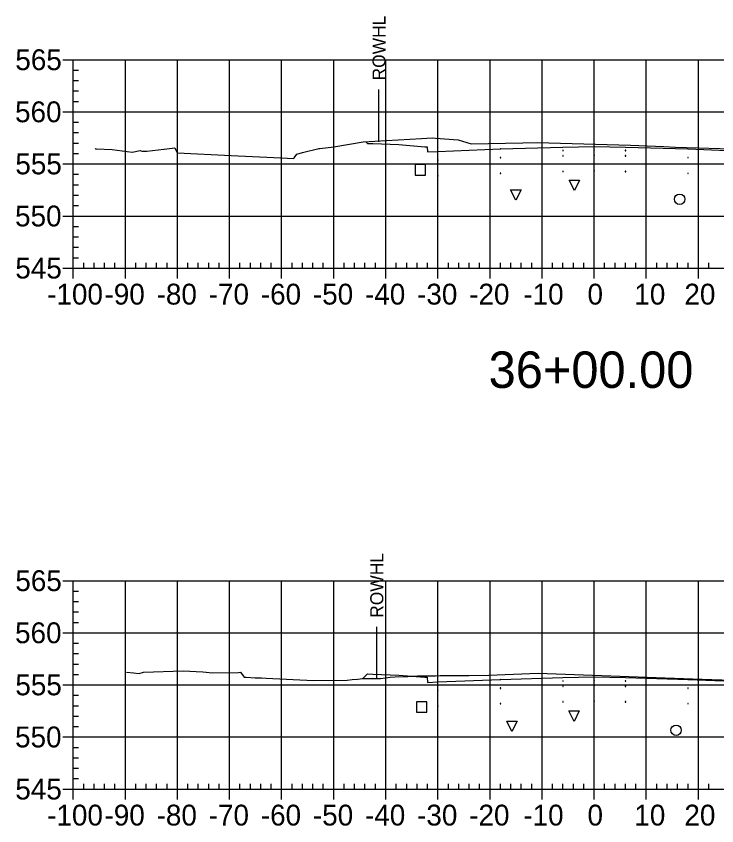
# Model space of a CAD drawing. Extents: x 708103 to 717568, y 374476 to 378707.
# Drawn here: x 710866 to 711000.5, y 377687.6 to 377843 of the extents above; entities that cross this region are included whole.
import ezdxf

# ---------------------------------------------------------------- set-up
doc = ezdxf.new("R2010")
doc.units = 0
for name, color, linetype in [('1', 7, 'Continuous'), ('10', 7, 'Continuous'), ('13', 7, 'Continuous'), ('14', 7, 'Continuous'), ('22', 7, 'Continuous'), ('57', 7, 'Continuous'), ('Existing', 7, 'Continuous'), ('XS_Right_of_Way', 7, 'Continuous')]:
    doc.layers.add(name, color=color, linetype=linetype)

msp = doc.modelspace()

# ---------------------------------------------------------------- linework, layer by layer
for points in [[(710970.93, 377817.14), (710971.03, 377817.14), (710971.03, 377817.24), (710970.93, 377817.24)], [(710970.93, 377816.14), (710971.03, 377816.14), (710971.03, 377816.24), (710970.93, 377816.24)], [(710976.93, 377817.26), (710977.03, 377817.26), (710977.03, 377817.36), (710976.93, 377817.36)], [(710976.93, 377816.26), (710977.03, 377816.26), (710977.03, 377816.36), (710976.93, 377816.36)], [(710982.93, 377817.14), (710983.03, 377817.14), (710983.03, 377817.24), (710982.93, 377817.24)], [(710982.93, 377816.14), (710983.03, 377816.14), (710983.03, 377816.24), (710982.93, 377816.24)], [(710946.93, 377815.3), (710947.03, 377815.3), (710947.03, 377815.4), (710946.93, 377815.4)], [(710958.93, 377815.78), (710959.03, 377815.78), (710959.03, 377815.88), (710958.93, 377815.88)], [(710994.93, 377815.78), (710995.03, 377815.78), (710995.03, 377815.88), (710994.93, 377815.88)], [(710970.93, 377813.14), (710971.03, 377813.14), (710971.03, 377813.24), (710970.93, 377813.24)], [(710976.93, 377813.26), (710977.03, 377813.26), (710977.03, 377813.36), (710976.93, 377813.36)], [(710982.93, 377813.14), (710983.03, 377813.14), (710983.03, 377813.24), (710982.93, 377813.24)], [(710946.93, 377812.3), (710947.03, 377812.3), (710947.03, 377812.4), (710946.93, 377812.4)], [(710958.93, 377812.78), (710959.03, 377812.78), (710959.03, 377812.88), (710958.93, 377812.88)], [(710994.93, 377812.78), (710995.03, 377812.78), (710995.03, 377812.88), (710994.93, 377812.88)], [(710970.93, 377715.32), (710971.03, 377715.32), (710971.03, 377715.42), (710970.93, 377715.42)], [(710976.93, 377715.44), (710977.03, 377715.44), (710977.03, 377715.54), (710976.93, 377715.54)], [(710982.93, 377715.32), (710983.03, 377715.32), (710983.03, 377715.42), (710982.93, 377715.42)], [(710946.93, 377713.48), (710947.03, 377713.48), (710947.03, 377713.58), (710946.93, 377713.58)], [(710958.93, 377713.96), (710959.03, 377713.96), (710959.03, 377714.06), (710958.93, 377714.06)], [(710970.93, 377714.32), (710971.03, 377714.32), (710971.03, 377714.42), (710970.93, 377714.42)], [(710976.93, 377714.44), (710977.03, 377714.44), (710977.03, 377714.54), (710976.93, 377714.54)], [(710982.93, 377714.32), (710983.03, 377714.32), (710983.03, 377714.42), (710982.93, 377714.42)], [(710994.93, 377713.96), (710995.03, 377713.96), (710995.03, 377714.06), (710994.93, 377714.06)], [(710946.93, 377710.48), (710947.03, 377710.48), (710947.03, 377710.58), (710946.93, 377710.58)], [(710958.93, 377710.96), (710959.03, 377710.96), (710959.03, 377711.06), (710958.93, 377711.06)], [(710970.93, 377711.32), (710971.03, 377711.32), (710971.03, 377711.42), (710970.93, 377711.42)], [(710976.93, 377711.44), (710977.03, 377711.44), (710977.03, 377711.54), (710976.93, 377711.54)], [(710982.93, 377711.32), (710983.03, 377711.32), (710983.03, 377711.42), (710982.93, 377711.42)], [(710994.93, 377710.96), (710995.03, 377710.96), (710995.03, 377711.06), (710994.93, 377711.06)]]:
    msp.add_lwpolyline(points, close=True)
at = {"layer": '1'}
for points in [[(710973.18, 377809.54), (710972.18, 377811.54), (710974.18, 377811.54)], [(710961.94, 377807.65), (710960.94, 377809.65), (710962.94, 377809.65)], [(710973.12, 377707.63), (710972.12, 377709.63), (710974.12, 377709.63)], [(710961.18, 377705.68), (710960.18, 377707.68), (710962.18, 377707.68)]]:
    msp.add_lwpolyline(points, close=True, dxfattribs=at)
at = {"layer": '10'}
for points in [[(710942.62, 377812.49), (710944.62, 377812.49), (710944.62, 377814.49), (710942.62, 377814.49)], [(710942.84, 377709.38), (710944.84, 377709.38), (710944.84, 377711.38), (710942.84, 377711.38)]]:
    msp.add_lwpolyline(points, close=True, dxfattribs=at)
at = {"layer": '13'}
for centre in [(710993.38, 377807.84), (710992.69, 377705.92)]:
    msp.add_circle(centre, 1, dxfattribs=at)
at = {"layer": '14'}
for points in [[(710933.17, 377818.89), (710933.17, 377818.94), (710933.17, 377818.89), (710933.12, 377818.89), (710933.17, 377818.89), (710933.17, 377818.84), (710933.17, 377818.89), (710933.22, 377818.89)], [(710976.98, 377817.98), (710976.98, 377818.03), (710976.98, 377817.98), (710976.93, 377817.98), (710976.98, 377817.98), (710976.98, 377817.93), (710976.98, 377817.98), (710977.03, 377817.98)], [(710946.98, 377817.02), (710946.98, 377817.07), (710946.98, 377817.02), (710946.93, 377817.02), (710946.98, 377817.02), (710946.98, 377816.97), (710946.98, 377817.02), (710947.03, 377817.02)], [(710958.98, 377817.5), (710958.98, 377817.55), (710958.98, 377817.5), (710958.93, 377817.5), (710958.98, 377817.5), (710958.98, 377817.45), (710958.98, 377817.5), (710959.03, 377817.5)], [(710994.98, 377817.5), (710994.98, 377817.55), (710994.98, 377817.5), (710994.93, 377817.5), (710994.98, 377817.5), (710994.98, 377817.45), (710994.98, 377817.5), (710995.03, 377817.5)], [(710932.59, 377715.86), (710932.59, 377715.91), (710932.59, 377715.86), (710932.54, 377715.86), (710932.59, 377715.86), (710932.59, 377715.81), (710932.59, 377715.86), (710932.64, 377715.86)], [(710946.98, 377715.19), (710946.98, 377715.24), (710946.98, 377715.19), (710946.93, 377715.19), (710946.98, 377715.19), (710946.98, 377715.14), (710946.98, 377715.19), (710947.03, 377715.19)], [(710958.98, 377715.67), (710958.98, 377715.72), (710958.98, 377715.67), (710958.93, 377715.67), (710958.98, 377715.67), (710958.98, 377715.62), (710958.98, 377715.67), (710959.03, 377715.67)], [(710976.98, 377716.15), (710976.98, 377716.2), (710976.98, 377716.15), (710976.93, 377716.15), (710976.98, 377716.15), (710976.98, 377716.1), (710976.98, 377716.15), (710977.03, 377716.15)], [(710994.98, 377715.67), (710994.98, 377715.72), (710994.98, 377715.67), (710994.93, 377715.67), (710994.98, 377715.67), (710994.98, 377715.62), (710994.98, 377715.67), (710995.03, 377715.67)]]:
    msp.add_lwpolyline(points, dxfattribs=at)
at = {"layer": '22'}
for points in [[(710933.17, 377818.89), (710933.48, 377818.58), (710934.48, 377818.54), (710939.48, 377818.34), (710944.48, 377817.94), (710944.9, 377817.94), (710944.98, 377816.94), (710946.98, 377817.02), (710958.98, 377817.5), (710970.98, 377817.86), (710976.98, 377817.98), (710982.98, 377817.86), (710994.98, 377817.5), (711006.98, 377817.02), (711008.98, 377816.94), (711009.07, 377817.94), (711009.48, 377817.94), (711014.48, 377818.34), (711019.48, 377818.54), (711020.48, 377818.58), (711021.32, 377817.75)], [(710932.59, 377715.86), (710933.48, 377716.75), (710934.48, 377716.71), (710939.48, 377716.51), (710944.48, 377716.11), (710944.9, 377716.11), (710944.98, 377715.11), (710946.98, 377715.19), (710958.98, 377715.67), (710970.98, 377716.03), (710976.98, 377716.15), (710982.98, 377716.03), (710994.98, 377715.67), (711006.98, 377715.19), (711008.98, 377715.11), (711009.07, 377716.11), (711009.48, 377716.11), (711014.48, 377716.51), (711019.48, 377716.71), (711020.48, 377716.75), (711020.83, 377716.41)]]:
    msp.add_lwpolyline(points, dxfattribs=at)
at = {"layer": '57'}
for p, q in [((710874.98, 377834.63), (710876.98, 377834.63)), ((710876.98, 377834.63), (711076.98, 377834.63)), ((710876.98, 377794.63), (710876.98, 377834.63)), ((710876.98, 377794.63), (710876.98, 377834.63)), ((710886.98, 377794.63), (710886.98, 377834.63)), ((710896.98, 377794.63), (710896.98, 377834.63)), ((710906.98, 377794.63), (710906.98, 377834.63)), ((710916.98, 377794.63), (710916.98, 377834.63)), ((710926.98, 377794.63), (710926.98, 377834.63)), ((710936.98, 377794.63), (710936.98, 377834.63)), ((710946.98, 377794.63), (710946.98, 377834.63)), ((710956.98, 377794.63), (710956.98, 377834.63)), ((710966.98, 377794.63), (710966.98, 377834.63)), ((710976.98, 377794.63), (710976.98, 377834.63)), ((710986.98, 377794.63), (710986.98, 377834.63)), ((710996.98, 377794.63), (710996.98, 377834.63)), ((710876.98, 377832.63), (710877.98, 377832.63)), ((710876.98, 377830.63), (710877.98, 377830.63)), ((710876.98, 377828.63), (710877.98, 377828.63)), ((710876.98, 377826.63), (710877.98, 377826.63)), ((710874.98, 377824.63), (710876.98, 377824.63)), ((710876.98, 377824.63), (711076.98, 377824.63)), ((710876.98, 377822.63), (710877.98, 377822.63)), ((710876.98, 377820.63), (710877.98, 377820.63)), ((710876.98, 377818.63), (710877.98, 377818.63)), ((710876.98, 377816.63), (710877.98, 377816.63)), ((710874.98, 377814.63), (710876.98, 377814.63)), ((710876.98, 377814.63), (711076.98, 377814.63)), ((710876.98, 377812.63), (710877.98, 377812.63)), ((710876.98, 377810.63), (710877.98, 377810.63)), ((710876.98, 377808.63), (710877.98, 377808.63)), ((710876.98, 377806.63), (710877.98, 377806.63)), ((710874.98, 377804.63), (710876.98, 377804.63)), ((710876.98, 377804.63), (711076.98, 377804.63)), ((710876.98, 377802.63), (710877.98, 377802.63)), ((710876.98, 377800.63), (710877.98, 377800.63)), ((710876.98, 377798.63), (710877.98, 377798.63)), ((710876.98, 377796.63), (710877.98, 377796.63)), ((710874.98, 377794.63), (710876.98, 377794.63)), ((710876.98, 377794.63), (711076.98, 377794.63)), ((710876.98, 377794.63), (711076.98, 377794.63)), ((710876.98, 377792.63), (710876.98, 377794.63)), ((710878.98, 377794.63), (710878.98, 377795.63)), ((710880.98, 377794.63), (710880.98, 377795.63)), ((710882.98, 377794.63), (710882.98, 377795.63)), ((710884.98, 377794.63), (710884.98, 377795.63)), ((710886.98, 377792.63), (710886.98, 377794.63)), ((710888.98, 377794.63), (710888.98, 377795.63)), ((710890.98, 377794.63), (710890.98, 377795.63)), ((710892.98, 377794.63), (710892.98, 377795.63)), ((710894.98, 377794.63), (710894.98, 377795.63)), ((710896.98, 377792.63), (710896.98, 377794.63)), ((710898.98, 377794.63), (710898.98, 377795.63)), ((710900.98, 377794.63), (710900.98, 377795.63)), ((710902.98, 377794.63), (710902.98, 377795.63)), ((710904.98, 377794.63), (710904.98, 377795.63)), ((710906.98, 377792.63), (710906.98, 377794.63)), ((710908.98, 377794.63), (710908.98, 377795.63)), ((710910.98, 377794.63), (710910.98, 377795.63)), ((710912.98, 377794.63), (710912.98, 377795.63)), ((710914.98, 377794.63), (710914.98, 377795.63)), ((710916.98, 377792.63), (710916.98, 377794.63)), ((710918.98, 377794.63), (710918.98, 377795.63)), ((710920.98, 377794.63), (710920.98, 377795.63)), ((710922.98, 377794.63), (710922.98, 377795.63)), ((710924.98, 377794.63), (710924.98, 377795.63)), ((710926.98, 377792.63), (710926.98, 377794.63)), ((710928.98, 377794.63), (710928.98, 377795.63)), ((710930.98, 377794.63), (710930.98, 377795.63)), ((710932.98, 377794.63), (710932.98, 377795.63)), ((710934.98, 377794.63), (710934.98, 377795.63)), ((710936.98, 377792.63), (710936.98, 377794.63)), ((710938.98, 377794.63), (710938.98, 377795.63)), ((710940.98, 377794.63), (710940.98, 377795.63)), ((710942.98, 377794.63), (710942.98, 377795.63)), ((710944.98, 377794.63), (710944.98, 377795.63)), ((710946.98, 377792.63), (710946.98, 377794.63)), ((710948.98, 377794.63), (710948.98, 377795.63)), ((710950.98, 377794.63), (710950.98, 377795.63)), ((710952.98, 377794.63), (710952.98, 377795.63)), ((710954.98, 377794.63), (710954.98, 377795.63)), ((710956.98, 377792.63), (710956.98, 377794.63)), ((710958.98, 377794.63), (710958.98, 377795.63)), ((710960.98, 377794.63), (710960.98, 377795.63)), ((710962.98, 377794.63), (710962.98, 377795.63)), ((710964.98, 377794.63), (710964.98, 377795.63)), ((710966.98, 377792.63), (710966.98, 377794.63)), ((710968.98, 377794.63), (710968.98, 377795.63)), ((710970.98, 377794.63), (710970.98, 377795.63)), ((710972.98, 377794.63), (710972.98, 377795.63)), ((710974.98, 377794.63), (710974.98, 377795.63)), ((710976.98, 377792.63), (710976.98, 377794.63)), ((710978.98, 377794.63), (710978.98, 377795.63)), ((710980.98, 377794.63), (710980.98, 377795.63)), ((710982.98, 377794.63), (710982.98, 377795.63)), ((710984.98, 377794.63), (710984.98, 377795.63)), ((710986.98, 377792.63), (710986.98, 377794.63)), ((710988.98, 377794.63), (710988.98, 377795.63)), ((710990.98, 377794.63), (710990.98, 377795.63)), ((710992.98, 377794.63), (710992.98, 377795.63)), ((710994.98, 377794.63), (710994.98, 377795.63)), ((710996.98, 377792.63), (710996.98, 377794.63)), ((710998.98, 377794.63), (710998.98, 377795.63)), ((710874.98, 377734.63), (710876.98, 377734.63)), ((710876.98, 377734.63), (711076.98, 377734.63)), ((710876.98, 377694.63), (710876.98, 377734.63)), ((710876.98, 377694.63), (710876.98, 377734.63)), ((710886.98, 377694.63), (710886.98, 377734.63)), ((710896.98, 377694.63), (710896.98, 377734.63)), ((710906.98, 377694.63), (710906.98, 377734.63)), ((710916.98, 377694.63), (710916.98, 377734.63)), ((710926.98, 377694.63), (710926.98, 377734.63)), ((710936.98, 377694.63), (710936.98, 377734.63)), ((710946.98, 377694.63), (710946.98, 377734.63)), ((710956.98, 377694.63), (710956.98, 377734.63)), ((710966.98, 377694.63), (710966.98, 377734.63)), ((710976.98, 377694.63), (710976.98, 377734.63)), ((710986.98, 377694.63), (710986.98, 377734.63)), ((710996.98, 377694.63), (710996.98, 377734.63)), ((710876.98, 377732.63), (710877.98, 377732.63)), ((710876.98, 377730.63), (710877.98, 377730.63)), ((710876.98, 377728.63), (710877.98, 377728.63)), ((710876.98, 377726.63), (710877.98, 377726.63)), ((710874.98, 377724.63), (710876.98, 377724.63)), ((710876.98, 377724.63), (711076.98, 377724.63)), ((710876.98, 377722.63), (710877.98, 377722.63)), ((710876.98, 377720.63), (710877.98, 377720.63)), ((710876.98, 377718.63), (710877.98, 377718.63)), ((710876.98, 377716.63), (710877.98, 377716.63)), ((710874.98, 377714.63), (710876.98, 377714.63)), ((710876.98, 377714.63), (711076.98, 377714.63)), ((710876.98, 377712.63), (710877.98, 377712.63)), ((710876.98, 377710.63), (710877.98, 377710.63)), ((710876.98, 377708.63), (710877.98, 377708.63)), ((710876.98, 377706.63), (710877.98, 377706.63)), ((710874.98, 377704.63), (710876.98, 377704.63)), ((710876.98, 377704.63), (711076.98, 377704.63)), ((710876.98, 377702.63), (710877.98, 377702.63)), ((710876.98, 377700.63), (710877.98, 377700.63)), ((710876.98, 377698.63), (710877.98, 377698.63)), ((710876.98, 377696.63), (710877.98, 377696.63)), ((710878.98, 377694.63), (710878.98, 377695.63)), ((710880.98, 377694.63), (710880.98, 377695.63)), ((710882.98, 377694.63), (710882.98, 377695.63)), ((710884.98, 377694.63), (710884.98, 377695.63)), ((710888.98, 377694.63), (710888.98, 377695.63)), ((710890.98, 377694.63), (710890.98, 377695.63)), ((710892.98, 377694.63), (710892.98, 377695.63)), ((710894.98, 377694.63), (710894.98, 377695.63)), ((710898.98, 377694.63), (710898.98, 377695.63)), ((710900.98, 377694.63), (710900.98, 377695.63)), ((710902.98, 377694.63), (710902.98, 377695.63)), ((710904.98, 377694.63), (710904.98, 377695.63)), ((710908.98, 377694.63), (710908.98, 377695.63)), ((710910.98, 377694.63), (710910.98, 377695.63)), ((710912.98, 377694.63), (710912.98, 377695.63)), ((710914.98, 377694.63), (710914.98, 377695.63)), ((710918.98, 377694.63), (710918.98, 377695.63)), ((710920.98, 377694.63), (710920.98, 377695.63)), ((710922.98, 377694.63), (710922.98, 377695.63)), ((710924.98, 377694.63), (710924.98, 377695.63)), ((710928.98, 377694.63), (710928.98, 377695.63)), ((710930.98, 377694.63), (710930.98, 377695.63)), ((710932.98, 377694.63), (710932.98, 377695.63)), ((710934.98, 377694.63), (710934.98, 377695.63)), ((710938.98, 377694.63), (710938.98, 377695.63)), ((710940.98, 377694.63), (710940.98, 377695.63)), ((710942.98, 377694.63), (710942.98, 377695.63)), ((710944.98, 377694.63), (710944.98, 377695.63)), ((710948.98, 377694.63), (710948.98, 377695.63)), ((710950.98, 377694.63), (710950.98, 377695.63)), ((710952.98, 377694.63), (710952.98, 377695.63)), ((710954.98, 377694.63), (710954.98, 377695.63)), ((710958.98, 377694.63), (710958.98, 377695.63)), ((710960.98, 377694.63), (710960.98, 377695.63)), ((710962.98, 377694.63), (710962.98, 377695.63)), ((710964.98, 377694.63), (710964.98, 377695.63)), ((710968.98, 377694.63), (710968.98, 377695.63)), ((710970.98, 377694.63), (710970.98, 377695.63)), ((710972.98, 377694.63), (710972.98, 377695.63)), ((710974.98, 377694.63), (710974.98, 377695.63)), ((710978.98, 377694.63), (710978.98, 377695.63)), ((710980.98, 377694.63), (710980.98, 377695.63)), ((710982.98, 377694.63), (710982.98, 377695.63)), ((710984.98, 377694.63), (710984.98, 377695.63)), ((710988.98, 377694.63), (710988.98, 377695.63)), ((710990.98, 377694.63), (710990.98, 377695.63)), ((710992.98, 377694.63), (710992.98, 377695.63)), ((710994.98, 377694.63), (710994.98, 377695.63)), ((710998.98, 377694.63), (710998.98, 377695.63)), ((710874.98, 377694.63), (710876.98, 377694.63)), ((710876.98, 377694.63), (711076.98, 377694.63)), ((710876.98, 377694.63), (711076.98, 377694.63)), ((710876.98, 377692.63), (710876.98, 377694.63)), ((710886.98, 377692.63), (710886.98, 377694.63)), ((710896.98, 377692.63), (710896.98, 377694.63)), ((710906.98, 377692.63), (710906.98, 377694.63)), ((710916.98, 377692.63), (710916.98, 377694.63)), ((710926.98, 377692.63), (710926.98, 377694.63)), ((710936.98, 377692.63), (710936.98, 377694.63)), ((710946.98, 377692.63), (710946.98, 377694.63)), ((710956.98, 377692.63), (710956.98, 377694.63)), ((710966.98, 377692.63), (710966.98, 377694.63)), ((710976.98, 377692.63), (710976.98, 377694.63)), ((710986.98, 377692.63), (710986.98, 377694.63)), ((710996.98, 377692.63), (710996.98, 377694.63))]:
    msp.add_line(p, q, dxfattribs=at)
at = {"layer": 'Existing'}
for points in [[(710881.21, 377817.56), (710881.28, 377817.54), (710881.45, 377817.54), (710884.48, 377817.38), (710888.31, 377816.87), (710889.84, 377817.18), (710890.17, 377817.06), (710891.13, 377817.09), (710894.38, 377817.46), (710894.43, 377817.48), (710896.47, 377817.73), (710896.87, 377816.87), (710896.98, 377816.73), (710907.26, 377816.26), (710915.45, 377815.88), (710919.31, 377815.65), (710919.38, 377815.78), (710919.87, 377816.52), (710920.96, 377816.83), (710924.13, 377817.59), (710924.34, 377817.59), (710927, 377817.92), (710932.61, 377818.86), (710943.82, 377819.5), (710945.9, 377819.65), (710946.53, 377819.55), (710950.86, 377819.23), (710951.71, 377819.01), (710953.38, 377818.47), (710963.29, 377818.68), (710966.02, 377818.73), (710983.95, 377818.25), (710990.36, 377817.98), (710992.56, 377817.87), (711005.46, 377817.44)], [(710887.17, 377717.06), (710888.54, 377716.93), (710889.61, 377716.8), (710890.47, 377717.06), (710898.07, 377717.3), (710901.84, 377717.14), (710903.71, 377716.92), (710908.68, 377717.03), (710909.1, 377717.07), (710909.6, 377716.36), (710909.78, 377716.09), (710910.19, 377716.08), (710911.88, 377716), (710913.11, 377715.95), (710914.01, 377715.91), (710923.12, 377715.48), (710929.53, 377715.56), (710930.49, 377715.65), (710931.52, 377715.75), (710932.59, 377715.86), (710935.95, 377715.88), (710936.89, 377715.99), (710937.82, 377716.09), (710938.76, 377716.17), (710941.2, 377716.21), (710942.12, 377716.28), (710943.04, 377716.34), (710943.92, 377716.39), (710946.49, 377716.37), (710947.38, 377716.4), (710948.97, 377716.45), (710949.7, 377716.46), (710950.34, 377716.46), (710951.4, 377716.45), (710952.92, 377716.43), (710956.74, 377716.49), (710966.24, 377716.89), (710995.82, 377715.8), (711005.19, 377715.49)]]:
    msp.add_lwpolyline(points, dxfattribs=at)
at = {"layer": 'XS_Right_of_Way'}
for p, q in [((710935.6, 377828.89), (710935.6, 377818.89)), ((710935.17, 377725.74), (710935.17, 377715.74))]:
    msp.add_line(p, q, dxfattribs=at)

# ---------------------------------------------------------------- texts
at = {"layer": '1'}
msp.add_text('36+00.00', height=7, dxfattribs=at).set_placement((710956.71, 377771.63))
at = {"layer": '14'}
for p in [(710934.45, 377818.49), (710934.45, 377817.82), (710939.45, 377817.62), (710934.45, 377716.66), (710934.45, 377716), (710939.45, 377715.8)]:
    msp.add_text('+', height=0.1, dxfattribs=at).set_placement(p)
at = {"layer": '57'}
for s, p in [('565', (710865.86, 377832.63)), ('560', (710865.81, 377822.63)), ('555', (710865.86, 377812.63)), ('550', (710865.81, 377802.63)), ('545', (710865.86, 377792.63)), ('-100', (710871.97, 377787.63)), ('-90', (710882.98, 377787.63)), ('-80', (710892.98, 377787.63)), ('-70', (710902.98, 377787.63)), ('-60', (710912.98, 377787.63)), ('-50', (710922.98, 377787.63)), ('-40', (710932.98, 377787.63)), ('-30', (710942.98, 377787.63)), ('-20', (710952.98, 377787.63)), ('-10', (710963.37, 377787.63)), ('0', (710975.69, 377787.63)), ('10', (710984.68, 377787.63)), ('20', (710994.29, 377787.63)), ('565', (710865.86, 377732.63)), ('560', (710865.81, 377722.63)), ('555', (710865.86, 377712.63)), ('550', (710865.81, 377702.63)), ('545', (710865.86, 377692.63)), ('-100', (710871.97, 377687.63)), ('-90', (710882.98, 377687.63)), ('-80', (710892.98, 377687.63)), ('-70', (710902.98, 377687.63)), ('-60', (710912.98, 377687.63)), ('-50', (710922.98, 377687.63)), ('-40', (710932.98, 377687.63)), ('-30', (710942.98, 377687.63)), ('-20', (710952.98, 377687.63)), ('-10', (710963.37, 377687.63)), ('0', (710975.69, 377687.63)), ('10', (710984.68, 377687.63)), ('20', (710994.29, 377687.63))]:
    msp.add_text(s, height=4, dxfattribs=at).set_placement(p)
at = {"layer": 'XS_Right_of_Way'}
for p in [(710936.92, 377830.65), (710936.49, 377727.5)]:
    msp.add_text('ROWHL', height=2.5, rotation=90, dxfattribs=at).set_placement(p)

doc.saveas('drawing.dxf')
